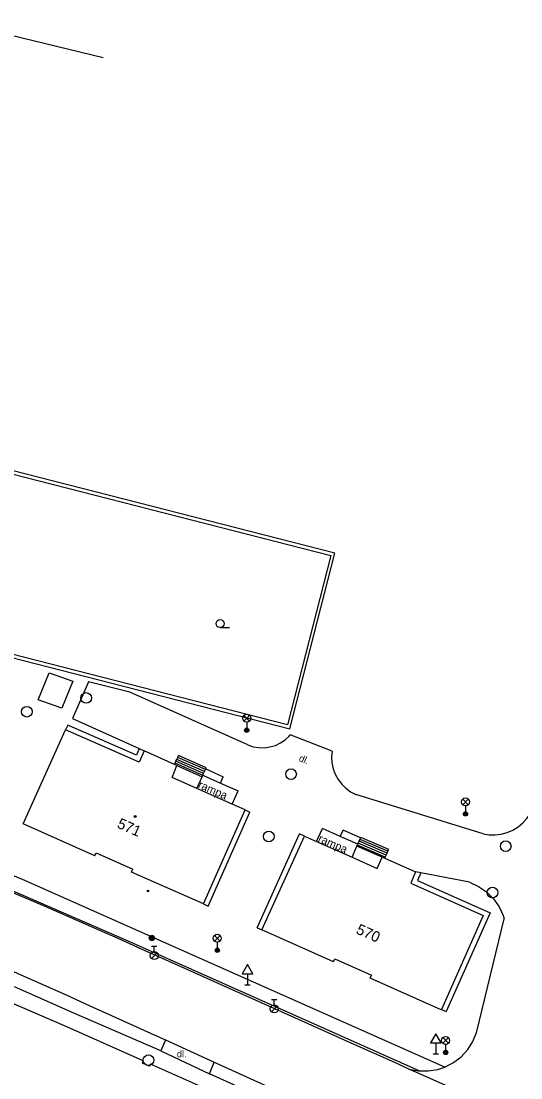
# Model space of a CAD drawing. Extents: x -540235 to -537963, y -1184915 to -1183660.
# Drawn here: x -538166.5 to -538119.7, y -1183946.2 to -1183847.2 of the extents above; entities that cross this region are included whole.
import ezdxf

# ---------------------------------------------------------------- set-up
doc = ezdxf.new("R2010")
doc.units = 0
for name, color, linetype in [('Vrstva 10', 7, 'Continuous'), ('Vrstva 11', 7, 'Continuous'), ('Vrstva 20', 7, 'Continuous'), ('Vrstva 25', 7, 'Continuous'), ('Vrstva 27', 7, 'Continuous'), ('Vrstva 28', 7, 'Continuous'), ('Vrstva 33', 7, 'Continuous'), ('Vrstva 34', 7, 'Continuous'), ('Vrstva 36', 7, 'Continuous'), ('Vrstva 39', 7, 'Continuous'), ('Vrstva 40', 7, 'Continuous'), ('Vrstva 41', 7, 'Continuous'), ('Vrstva 47', 7, 'Continuous'), ('Vrstva 5', 7, 'Continuous'), ('Vrstva 7', 7, 'Continuous')]:
    doc.layers.add(name, color=color, linetype=linetype)

msp = doc.modelspace()

# ---------------------------------------------------------------- linework, layer by layer
at = {"layer": 'Vrstva 10'}
for p, q in [((-538146.758, -1183920.564), (-538146.2, -1183919.32)), ((-538138.833, -1183924.07), (-538138.29, -1183922.85)), ((-538142.759, -1183939.739), (-538148.123, -1183937.327)), ((-538157.988, -1183940.395), (-538154.069, -1183942.171)), ((-538135.608, -1183942.958), (-538142.759, -1183939.739)), ((-538131.52, -1183944.792), (-538135.608, -1183942.958)), ((-538130.183, -1183945.389), (-538131.52, -1183944.792))]:
    msp.add_line(p, q, dxfattribs=at)
for points in [[(-538149.491, -1183917.843), (-538147.842, -1183918.583), (-538146.2, -1183919.32)], [(-538134.977, -1183924.324), (-538136.615, -1183923.595), (-538138.29, -1183922.85)], [(-538166.401, -1183929.237), (-538168.355, -1183928.397), (-538170.068, -1183927.667), (-538171.567, -1183927.031)], [(-538164.25, -1183930.17), (-538165.36, -1183929.687), (-538166.401, -1183929.237)], [(-538155.169, -1183934.175), (-538157.437, -1183933.168), (-538159.138, -1183932.415), (-538161.693, -1183931.289), (-538164.25, -1183930.17)], [(-538173.638, -1183933.489), (-538172.034, -1183934.168), (-538171.24, -1183934.508), (-538170.833, -1183934.682), (-538169.933, -1183935.07), (-538168.586, -1183935.657), (-538167.24, -1183936.25), (-538166.55, -1183936.557), (-538164.695, -1183937.382)], [(-538148.123, -1183937.327), (-538152.148, -1183935.523), (-538155.169, -1183934.175)], [(-538164.695, -1183937.382), (-538162.312, -1183938.448), (-538160.079, -1183939.452), (-538157.988, -1183940.395)], [(-538154.069, -1183942.171), (-538152.987, -1183942.664), (-538148.42, -1183944.742), (-538140.365, -1183948.408)], [(-538121.87, -1183949.08), (-538124.524, -1183947.908), (-538127.009, -1183946.805), (-538129.338, -1183945.767), (-538130.183, -1183945.389)]]:
    msp.add_lwpolyline(points, dxfattribs=at)
at = {"layer": 'Vrstva 11'}
for p, q in [((-538160.22, -1183909.09), (-538161.69, -1183912.54)), ((-538156.33, -1183910.07), (-538160.22, -1183909.09)), ((-538145.28, -1183915.01), (-538156.33, -1183910.07)), ((-538161.69, -1183912.54), (-538155.445, -1183915.355)), ((-538162.13, -1183913.161), (-538162.369, -1183913.603)), ((-538155.709, -1183915.961), (-538162.13, -1183913.161)), ((-538137.39, -1183915.6), (-538141.3, -1183914.07)), ((-538155.445, -1183915.355), (-538155.709, -1183915.961)), ((-538155.445, -1183915.355), (-538154.99, -1183915.56)), ((-538149.506, -1183917.877), (-538152.096, -1183916.727)), ((-538149.425, -1183917.695), (-538152.015, -1183916.545)), ((-538149.343, -1183917.512), (-538151.933, -1183916.362)), ((-538149.261, -1183917.33), (-538151.851, -1183916.18)), ((-538149.179, -1183917.147), (-538151.769, -1183915.997)), ((-538166.383, -1183927.611), (-538192.283, -1183916.985)), ((-538151.93, -1183916.94), (-538149.562, -1183918.002)), ((-538149.229, -1183917.26), (-538147.58, -1183918)), ((-538147.842, -1183918.583), (-538147.58, -1183918)), ((-538123.24, -1183923.34), (-538135.15, -1183919.67)), ((-538149.003, -1183930.113), (-538145.083, -1183921.313)), ((-538145.54, -1183921.11), (-538145.083, -1183921.313)), ((-538144.415, -1183932.143), (-538140.435, -1183923.353)), ((-538139.98, -1183923.56), (-538140.435, -1183923.353)), ((-538136.615, -1183923.595), (-538136.35, -1183923)), ((-538134.712, -1183923.729), (-538136.35, -1183923)), ((-538132.08, -1183924.8), (-538134.69, -1183923.68)), ((-538132.69, -1183925.52), (-538135.057, -1183924.504)), ((-538132.405, -1183925.531), (-538135.015, -1183924.411)), ((-538132.323, -1183925.348), (-538134.934, -1183924.228)), ((-538132.242, -1183925.165), (-538134.852, -1183924.045)), ((-538132.161, -1183924.982), (-538134.771, -1183923.862)), ((-538175.79, -1183924.99), (-538156.58, -1183933.33)), ((-538126.83, -1183945.203), (-538166.383, -1183927.611)), ((-538129.079, -1183927.007), (-538129.371, -1183927.711)), ((-538129.371, -1183927.711), (-538122.57, -1183930.747)), ((-538149.44, -1183929.9), (-538149.003, -1183930.113)), ((-538122.57, -1183930.747), (-538126.693, -1183940.013)), ((-538123.82, -1183941.86), (-538121.259, -1183931.307)), ((-538144.415, -1183932.143), (-538143.96, -1183932.35)), ((-538156.58, -1183933.33), (-538138.49, -1183941.41)), ((-538161.58, -1183940.15), (-538167.14, -1183937.7)), ((-538162.25, -1183941.43), (-538167.74, -1183939.07)), ((-538153.43, -1183943.67), (-538161.58, -1183940.15)), ((-538127.15, -1183939.81), (-538126.693, -1183940.013)), ((-538155.09, -1183944.62), (-538162.25, -1183941.43)), ((-538138.49, -1183941.41), (-538129.199, -1183945.559)), ((-538152.987, -1183942.664), (-538153.43, -1183943.67)), ((-538153.43, -1183943.67), (-538148.87, -1183945.83)), ((-538149.34, -1183947.19), (-538154.39, -1183944.92)), ((-538148.87, -1183945.83), (-538148.42, -1183944.742)), ((-538136.08, -1183951.61), (-538148.87, -1183945.83))]:
    msp.add_line(p, q, dxfattribs=at)
for points in [[(-538145.28, -1183915.01), (-538144.779, -1183915.175), (-538144.258, -1183915.263), (-538143.73, -1183915.271), (-538143.207, -1183915.2), (-538142.7, -1183915.05), (-538142.222, -1183914.826), (-538141.784, -1183914.532), (-538141.394, -1183914.175), (-538141.3, -1183914.07)], [(-538137.39, -1183915.6), (-538137.433, -1183916.151), (-538137.396, -1183916.702), (-538137.28, -1183917.242), (-538137.088, -1183917.76), (-538136.822, -1183918.245), (-538136.49, -1183918.686), (-538136.097, -1183919.075), (-538135.653, -1183919.403), (-538135.165, -1183919.663), (-538135.15, -1183919.67)], [(-538152.148, -1183916.842), (-538152.096, -1183916.727), (-538152.015, -1183916.545), (-538151.933, -1183916.362), (-538151.851, -1183916.18), (-538151.769, -1183915.997)], [(-538150.049, -1183919.087), (-538149.562, -1183918.002), (-538149.506, -1183917.877), (-538149.491, -1183917.843), (-538149.425, -1183917.695), (-538149.343, -1183917.512), (-538149.261, -1183917.33), (-538149.229, -1183917.26), (-538149.179, -1183917.147)], [(-538123.24, -1183923.34), (-538122.675, -1183923.427), (-538122.103, -1183923.435), (-538121.536, -1183923.363), (-538120.984, -1183923.213), (-538120.459, -1183922.987), (-538119.97, -1183922.69), (-538119.528, -1183922.328), (-538119.14, -1183921.908), (-538118.815, -1183921.438), (-538118.71, -1183921.25)], [(-538135.52, -1183925.545), (-538135.057, -1183924.504), (-538135.015, -1183924.411), (-538134.977, -1183924.324), (-538134.934, -1183924.228), (-538134.852, -1183924.045), (-538134.771, -1183923.862), (-538134.712, -1183923.729), (-538134.69, -1183923.68)], [(-538132.448, -1183925.628), (-538132.405, -1183925.531), (-538132.323, -1183925.348), (-538132.242, -1183925.165), (-538132.161, -1183924.982), (-538132.08, -1183924.8)], [(-538124.52, -1183927.89), (-538129.079, -1183927.007), (-538129.58, -1183926.91)], [(-538124.52, -1183927.89), (-538123.687, -1183928.272), (-538122.933, -1183928.794), (-538122.281, -1183929.438), (-538121.751, -1183930.185), (-538121.358, -1183931.014), (-538121.259, -1183931.307)], [(-538126.83, -1183945.203), (-538126.023, -1183944.788), (-538125.3, -1183944.237), (-538124.686, -1183943.569), (-538124.198, -1183942.803), (-538123.851, -1183941.963), (-538123.82, -1183941.86)], [(-538154.39, -1183944.92), (-538154.52, -1183945.13), (-538155.15, -1183944.84), (-538155.09, -1183944.62)], [(-538130.183, -1183945.389), (-538129.29, -1183945.558), (-538129.199, -1183945.559), (-538128.38, -1183945.568), (-538127.483, -1183945.419), (-538126.83, -1183945.203)]]:
    msp.add_lwpolyline(points, dxfattribs=at)
at = {"layer": 'Vrstva 20'}
for radius in [0.075, 0.0204]:
    msp.add_circle((-538154.63, -1183928.7), radius, dxfattribs=at)
at = {"layer": 'Vrstva 25'}
for radius in [0.25, 0.2, 0.15, 0.1, 0.05]:
    msp.add_circle((-538154.27, -1183933.1), radius, dxfattribs=at)
at = {"layer": 'Vrstva 27'}
for centre in [(-538160.42, -1183910.61), (-538165.98, -1183911.9), (-538141.23, -1183917.75), (-538143.32, -1183923.6), (-538121.12, -1183924.5), (-538122.36, -1183928.85), (-538154.58, -1183944.56)]:
    msp.add_circle(centre, 0.5, dxfattribs=at)
at = {"layer": 'Vrstva 28'}
for p, q in [((-538154.298, -1183935.022), (-538153.768, -1183934.492)), ((-538154.29, -1183933.875), (-538153.79, -1183933.875)), ((-538154.04, -1183934.375), (-538154.04, -1183933.875)), ((-538143.068, -1183940.022), (-538142.538, -1183939.492)), ((-538143.06, -1183938.875), (-538142.56, -1183938.875)), ((-538142.81, -1183939.375), (-538142.81, -1183938.875))]:
    msp.add_line(p, q, dxfattribs=at)
for centre in [(-538154.04, -1183934.75), (-538142.81, -1183939.75)]:
    msp.add_circle(centre, 0.375, dxfattribs=at)
at = {"layer": 'Vrstva 33'}
for p, q in [((-538145.645, -1183912.77), (-538145.115, -1183912.24)), ((-538145.645, -1183912.24), (-538145.115, -1183912.77)), ((-538145.38, -1183912.88), (-538145.38, -1183913.63)), ((-538125.155, -1183920.62), (-538124.625, -1183920.09)), ((-538125.155, -1183920.09), (-538124.625, -1183920.62)), ((-538124.89, -1183920.73), (-538124.89, -1183921.48)), ((-538148.405, -1183933.4), (-538147.875, -1183932.87)), ((-538148.405, -1183932.87), (-538147.875, -1183933.4)), ((-538148.14, -1183933.51), (-538148.14, -1183934.26)), ((-538127.015, -1183942.98), (-538126.485, -1183942.45)), ((-538127.015, -1183942.45), (-538126.485, -1183942.98)), ((-538126.75, -1183943.09), (-538126.75, -1183943.84))]:
    msp.add_line(p, q, dxfattribs=at)
for centre, radius in [((-538145.38, -1183912.505), 0.375), ((-538145.38, -1183913.63), 0.2), ((-538145.38, -1183913.63), 0.1445), ((-538145.38, -1183913.63), 0.0876), ((-538124.89, -1183920.355), 0.375), ((-538124.89, -1183921.48), 0.2), ((-538124.89, -1183921.48), 0.1445), ((-538124.89, -1183921.48), 0.0876), ((-538148.14, -1183933.135), 0.375), ((-538148.14, -1183934.26), 0.2), ((-538148.14, -1183934.26), 0.1445), ((-538148.14, -1183934.26), 0.0876), ((-538126.75, -1183942.715), 0.375), ((-538126.75, -1183943.84), 0.2), ((-538126.75, -1183943.84), 0.1445), ((-538126.75, -1183943.84), 0.0876)]:
    msp.add_circle(centre, radius, dxfattribs=at)
at = {"layer": 'Vrstva 34'}
for p, q in [((-538145.3, -1183936.472), (-538145.3, -1183937.49)), ((-538145.55, -1183937.49), (-538145.05, -1183937.49)), ((-538127.66, -1183942.942), (-538127.66, -1183943.96)), ((-538127.91, -1183943.96), (-538127.41, -1183943.96))]:
    msp.add_line(p, q, dxfattribs=at)
for points in [[(-538145.8, -1183936.472), (-538144.8, -1183936.472), (-538145.3, -1183935.606)], [(-538128.16, -1183942.942), (-538127.16, -1183942.942), (-538127.66, -1183942.076)]]:
    msp.add_lwpolyline(points, close=True, dxfattribs=at)
at = {"layer": 'Vrstva 36'}
msp.add_line((-538147.876, -1183904.018), (-538147.001, -1183904.018), dxfattribs=at)
msp.add_circle((-538147.8761, -1183903.6429), 0.375, dxfattribs=at)
at = {"layer": 'Vrstva 39'}
for radius in [0.09, 0.0398]:
    msp.add_circle((-538155.834, -1183921.711), radius, dxfattribs=at)
at = {"layer": 'Vrstva 5'}
for p, q in [((-538158.84, -1183850.6), (-538172.96, -1183847.17)), ((-538164.92, -1183910.77), (-538163.88, -1183908.25)), ((-538163.88, -1183908.25), (-538161.68, -1183909.05)), ((-538161.68, -1183909.05), (-538162.71, -1183911.57)), ((-538162.71, -1183911.57), (-538164.92, -1183910.77)), ((-538166.32, -1183922.42), (-538162.369, -1183913.603)), ((-538155.45, -1183916.62), (-538162.369, -1183913.603)), ((-538154.99, -1183915.56), (-538155.45, -1183916.62)), ((-538152.148, -1183916.842), (-538154.99, -1183915.56)), ((-538152.36, -1183918.05), (-538151.93, -1183916.94)), ((-538151.93, -1183916.94), (-538152.148, -1183916.842)), ((-538150.049, -1183919.087), (-538152.36, -1183918.05)), ((-538146.758, -1183920.564), (-538150.049, -1183919.087)), ((-538145.54, -1183921.11), (-538146.758, -1183920.564)), ((-538149.44, -1183929.9), (-538145.54, -1183921.11)), ((-538159.603, -1183925.404), (-538166.32, -1183922.42)), ((-538143.96, -1183932.35), (-538139.98, -1183923.56)), ((-538139.98, -1183923.56), (-538138.833, -1183924.07)), ((-538138.833, -1183924.07), (-538135.52, -1183925.545)), ((-538159.603, -1183925.404), (-538159.481, -1183925.129)), ((-538159.481, -1183925.129), (-538156.054, -1183926.652)), ((-538135.52, -1183925.545), (-538133.17, -1183926.59)), ((-538133.17, -1183926.59), (-538132.69, -1183925.52)), ((-538132.69, -1183925.52), (-538132.448, -1183925.628)), ((-538132.448, -1183925.628), (-538129.58, -1183926.91)), ((-538156.176, -1183926.926), (-538156.054, -1183926.652)), ((-538149.44, -1183929.9), (-538156.176, -1183926.926)), ((-538129.58, -1183926.91), (-538130.02, -1183927.97)), ((-538130.02, -1183927.97), (-538123.23, -1183931)), ((-538123.23, -1183931), (-538127.15, -1183939.81)), ((-538137.246, -1183935.343), (-538143.96, -1183932.35)), ((-538137.246, -1183935.343), (-538137.124, -1183935.068)), ((-538137.124, -1183935.068), (-538133.699, -1183936.594)), ((-538133.821, -1183936.869), (-538133.699, -1183936.594)), ((-538127.162, -1183939.837), (-538133.821, -1183936.869)), ((-538127.15, -1183939.81), (-538127.162, -1183939.837))]:
    msp.add_line(p, q, dxfattribs=at)
at = {"layer": 'Vrstva 7'}
for p, q in [((-538137.142, -1183897.047), (-538169.33, -1183888.81)), ((-538169.394, -1183889.104), (-538137.507, -1183897.263)), ((-538137.507, -1183897.263), (-538141.566, -1183913.125)), ((-538141.35, -1183913.49), (-538137.142, -1183897.047)), ((-538141.566, -1183913.125), (-538185.692, -1183901.832)), ((-538186.05, -1183902.05), (-538141.35, -1183913.49))]:
    msp.add_line(p, q, dxfattribs=at)

# ---------------------------------------------------------------- texts
at = {"layer": 'Vrstva 40'}
msp.add_text('dl.', height=0.65, rotation=335.544222, dxfattribs=at).set_placement((-538140.56, -1183916.486))
msp.add_text('dl.', height=0.65, dxfattribs=at).set_placement((-538151.933, -1183944.3))
at = {"layer": 'Vrstva 41'}
for p in [(-538150.001, -1183919.002), (-538138.759, -1183924.043)]:
    msp.add_text('rampa', height=0.75, rotation=336.219433, dxfattribs=at).set_placement(p)
at = {"layer": 'Vrstva 47'}
for s, rotation, p in [('571', 336.039061, (-538157.6, -1183922.737)), ('570', 335.973408, (-538135.214, -1183932.656))]:
    msp.add_text(s, height=1, rotation=rotation, dxfattribs=at).set_placement(p)

doc.saveas('drawing.dxf')
